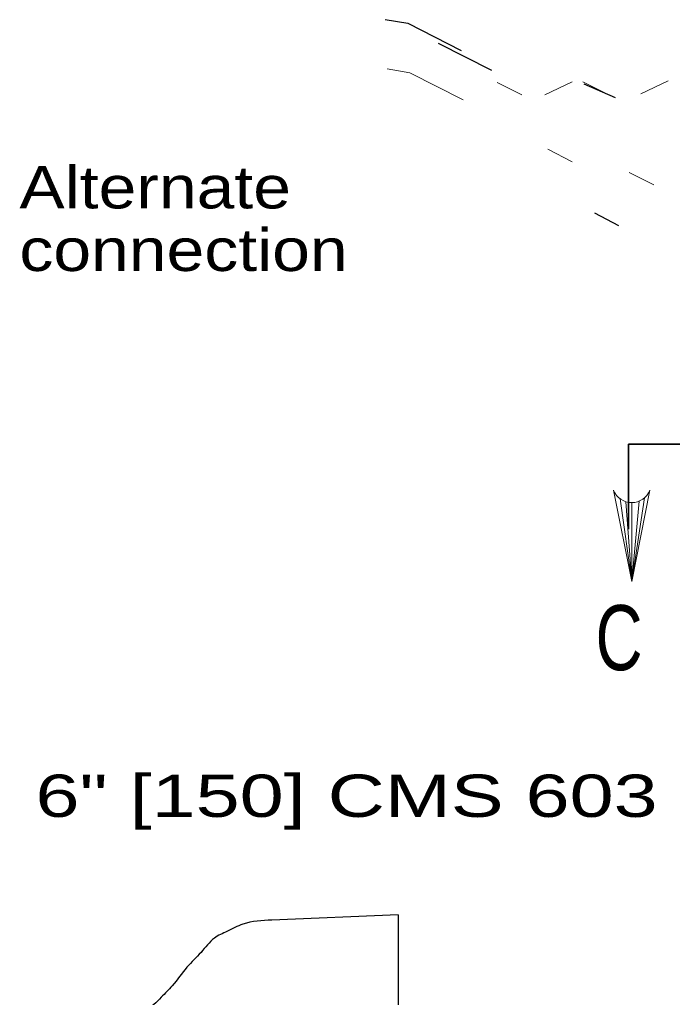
# Model space of a CAD drawing. Extents: x 1083.1 to 1117.1, y 719.4 to 741.4.
# Drawn here: x 1094.547 to 1096.956, y 727.471 to 731.077 of the extents above; entities that cross this region are included whole.
import ezdxf
from ezdxf.enums import TextEntityAlignment as Align

# ---------------------------------------------------------------- set-up
doc = ezdxf.new("R2010")
doc.units = 0
doc.header["$LTSCALE"] = 0.062
doc.layers.add('1', color=7, linetype='Continuous', lineweight=13)

msp = doc.modelspace()

# ---------------------------------------------------------------- linework, layer by layer
at = {"layer": '1', "lineweight": 25}
for p, q in [((1096.09158, 730.99025), (1096.28858, 730.89025)), ((1096.629, 730.841), (1096.74525, 730.78958)), ((1096.66792, 730.36425), (1096.75742, 730.31792)), ((1095.94383, 727.77608), (1095.47842, 727.75617)), ((1095.94383, 727.77608), (1095.94383, 725.21108))]:
    msp.add_line(p, q, dxfattribs=at)
at = {"layer": '1'}
for p, q in [((1096.30942, 730.84542), (1096.39983, 730.79975)), ((1096.5855, 730.84833), (1096.48517, 730.80008)), ((1096.62558, 730.84775), (1096.71608, 730.802)), ((1096.93983, 730.85167), (1096.8395, 730.80342)), ((1096.496, 730.59942), (1096.5855, 730.55308)), ((1096.79642, 730.514), (1096.88692, 730.46825)), ((1096.76325, 729.30967), (1096.80583, 729.00525)), ((1096.78433, 729.29933), (1096.80583, 729.00525)), ((1096.85292, 729.31325), (1096.80583, 729.00525)), ((1096.83325, 729.30158), (1096.80583, 729.00525)), ((1096.80583, 729.29625), (1096.80583, 729.00525))]:
    msp.add_line(p, q, dxfattribs=at)
at = {"layer": '1', "lineweight": 35}
for q in [(1096.79417, 729.19842), (1099.41317, 729.51175)]:
    msp.add_line((1096.79417, 729.51175), q, dxfattribs=at)
at = {"layer": '1', "lineweight": 25}
msp.add_lwpolyline([(1095.89583, 731.0775), (1095.97992, 731.06358), (1096.17692, 730.96358)], dxfattribs=at)
at = {"layer": '1'}
for points in [[(1095.90333, 730.89533), (1095.9875, 730.88142), (1096.1845, 730.78142)], [(1096.87317, 729.3415), (1096.80583, 729.00525), (1096.73858, 729.3415)]]:
    msp.add_lwpolyline(points, dxfattribs=at)
msp.add_arc((1096.8058, 729.36868), 0.07258, 202.08782, 337.91395, dxfattribs=at)
at = {"layer": '1', "lineweight": 25}
msp.add_spline([(1095.47842, 727.75617), (1095.37117, 727.74158), (1095.3125, 727.71475), (1095.266, 727.68983), (1095.21683, 727.63733), (1095.16492, 727.583), (1095.11067, 727.514), (1095.06992, 727.47175), (1095.04233, 727.4455), (1095.0055, 727.42883), (1094.97975, 727.42125)], degree=3, dxfattribs=at)

# ---------------------------------------------------------------- texts
at = {"layer": '1'}
for s, width, p in [('Alternate', 1.2, (1094.54675, 730.381)), ('connection', 1.2, (1094.54675, 730.15025)), ('6" [150] CMS 603 Conduit', 1.4, (1094.60608, 728.13692))]:
    msp.add_text(s, height=0.156, dxfattribs=dict(at, width=width)).set_placement(p)
at = {"layer": '1', "width": 0.75}
msp.add_text('C', height=0.24, dxfattribs=at).set_placement((1096.75908, 728.678), align=Align.CENTER)

doc.saveas('drawing.dxf')
